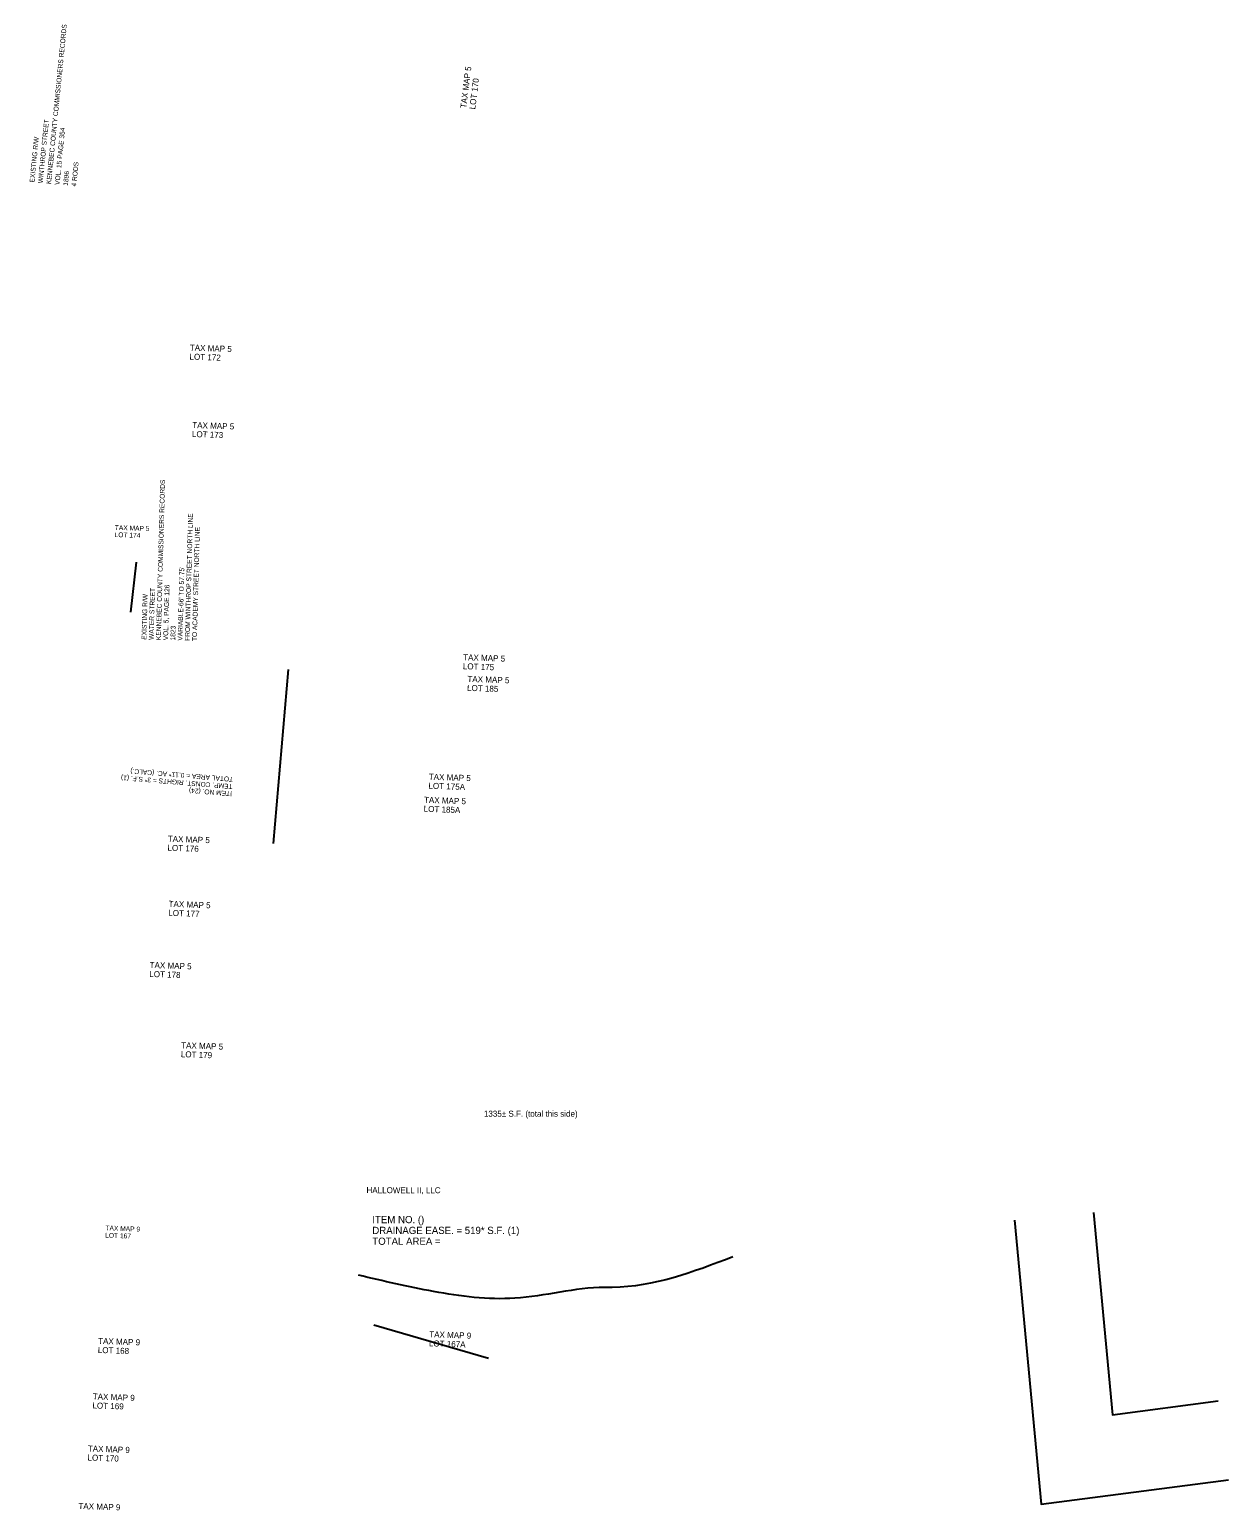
# Model space of a CAD drawing. Extents: x 1133267 to 1139526, y 528613 to 531538.
# Drawn here: x 1137644 to 1138142, y 529871 to 530487 of the extents above; entities that cross this region are included whole.
import ezdxf

# ---------------------------------------------------------------- set-up
doc = ezdxf.new("R2010")
doc.units = 0
for name, color, linetype in [('E_Property_Line', 7, 'Continuous'), ('E_ROW_TieLine', 7, 'Continuous'), ('P_Ease_Perm_Drainage_Line', 7, 'Continuous'), ('PROPERTY NOTES', 7, 'Continuous'), ('PRP OWNER NAMES', 7, 'Continuous'), ('PRPTY SETUPS', 7, 'Continuous'), ('ROW REFERENCES', 7, 'Continuous')]:
    doc.layers.add(name, color=color, linetype=linetype)

msp = doc.modelspace()

# ---------------------------------------------------------------- linework, layer by layer
at = {"layer": 'E_Property_Line'}
for p, q in [((1137685.86, 530244.99), (1137688.14, 530265.71)), ((1137745.12, 530148.68), (1137751.44, 530221.17))]:
    msp.add_line(p, q, dxfattribs=at)
at = {"layer": 'E_ROW_TieLine'}
msp.add_line((1137834.58, 529934.58), (1137787, 529948.38), dxfattribs=at)
for points in [[(1138086.29, 529995.24), (1138094.25, 529911.19), (1138138.21, 529916.91)], [(1138053.43, 529992.13), (1138064.62, 529874.06), (1138142.46, 529884.18)]]:
    msp.add_lwpolyline(points, dxfattribs=at)
msp.add_spline([(1137936.27, 529976.83), (1137886.15, 529964.15), (1137883.05, 529964.15), (1137845.61, 529959.64), (1137811.82, 529962.46), (1137780.57, 529969.22)], degree=3, dxfattribs=at)

# ---------------------------------------------------------------- texts
at = {"layer": 'P_Ease_Perm_Drainage_Line'}
msp.add_text('1335± S.F. (total this side)', height=2.5, dxfattribs=at).set_placement((1137832.73, 530035.13))
at = {"layer": 'PROPERTY NOTES'}
for s, height, rotation, p in [('TAX MAP 5', 2.5, 82.95839, (1137825.38, 530454.39)), ('LOT 170', 2.5, 82.95839, (1137829.11, 530453.93)), ('LOT 172', 2.5, 357.92813, (1137710.21, 530350.01)), ('TAX MAP 5', 2.5, 357.92813, (1137710.34, 530353.76)), ('LOT 173', 2.5, 357.92813, (1137711.23, 530317.8)), ('TAX MAP 5', 2.5, 357.92813, (1137711.37, 530321.55)), ('LOT 174', 2, 357.92813, (1137679.03, 530276.2)), ('TAX MAP 5', 2, 357.92813, (1137679.13, 530279.2)), ('LOT 175', 2.5, 357.92813, (1137823.94, 530221.26)), ('TAX MAP 5', 2.5, 357.92813, (1137824.07, 530225)), ('TAX MAP 5', 2.5, 357.92813, (1137825.83, 530215.99)), ('LOT 185', 2.5, 357.92813, (1137825.69, 530212.24)), ('LOT 175A', 2.5, 357.92813, (1137809.62, 530171.56)), ('TAX MAP 5', 2.5, 357.92813, (1137809.76, 530175.3)), ('TAX MAP 5', 2.5, 357.92813, (1137807.77, 530165.69)), ('LOT 185A', 2.5, 357.92813, (1137807.64, 530161.94)), ('LOT 176', 2.5, 357.92813, (1137701.05, 530145.76)), ('TAX MAP 5', 2.5, 357.92813, (1137701.19, 530149.51)), ('TAX MAP 5', 2.5, 357.92813, (1137701.52, 530122.44)), ('LOT 177', 2.5, 357.92813, (1137701.38, 530118.7)), ('TAX MAP 5', 2.5, 357.92813, (1137693.62, 530097.03)), ('LOT 178', 2.5, 357.92813, (1137693.48, 530093.28)), ('LOT 179', 2.5, 357.92813, (1137706.61, 530059.91)), ('TAX MAP 5', 2.5, 357.92813, (1137706.74, 530063.65)), ('TAX MAP 9', 2, 357.92813, (1137675.25, 529987.89)), ('LOT 167', 2, 357.92813, (1137675.14, 529984.87)), ('TAX MAP 9', 2.5, 357.92813, (1137809.95, 529943.44)), ('LOT 168', 2.5, 357.92813, (1137672.06, 529936.91)), ('TAX MAP 9', 2.5, 357.92813, (1137672.2, 529940.66)), ('LOT 167A', 2.5, 357.92813, (1137809.82, 529939.69)), ('TAX MAP 9', 2.5, 357.92813, (1137669.97, 529917.58)), ('LOT 169', 2.5, 357.92813, (1137669.83, 529913.84)), ('TAX MAP 9', 2.5, 357.92813, (1137667.92, 529895.93)), ('LOT 170', 2.5, 357.92813, (1137667.78, 529892.18)), ('TAX MAP 9', 2.5, 357.92813, (1137663.99, 529872.06))]:
    msp.add_text(s, height=height, rotation=rotation, dxfattribs=at).set_placement(p)
at = {"layer": 'PRP OWNER NAMES'}
msp.add_text('HALLOWELL II, LLC', height=2.5, rotation=359.95317, dxfattribs=at).set_placement((1137783.87, 530003.34))
at = {"layer": 'PRPTY SETUPS'}
for s, p in [('TOTAL AREA = 0.11* AC. (CALC.)', (1137728.48, 530176.38)), ('TEMP. CONST. RIGHTS = 3* S.F. (1)', (1137728.23, 530173.37)), ('ITEM NO. (24)', (1137727.99, 530170.36))]:
    msp.add_text(s, height=2, rotation=175.39044, dxfattribs=at).set_placement(p)
for s, p in [('ITEM NO. ()', (1137786.3, 529990.86)), ('DRAINAGE EASE. = 519* S.F. (1)', (1137786.3, 529986.36)), ('TOTAL AREA =', (1137786.3, 529981.86))]:
    msp.add_text(s, height=3, dxfattribs=at).set_placement(p)
at = {"layer": 'ROW REFERENCES'}
for s, rotation, p in [('KENNEBEC COUNTY COMMISSIONERS RECORDS', 84.34851, (1137652.65, 530422.89)), ('WINTHROP STREET', 84.34851, (1137649.17, 530423.24)), ('VOL. 15 PAGE 354', 84.34851, (1137656.14, 530422.55)), ('EXISTING R/W', 84.34851, (1137645.69, 530423.58)), ('4 RODS', 84.34851, (1137663.1, 530421.86)), ('1896', 84.34851, (1137659.62, 530422.21)), ('KENNEBEC COUNTY COMMISSIONERS RECORDS', 88.47432, (1137698.3, 530233.31)), ('FROM WINTHROP STREET NORTH LINE', 88.47432, (1137710.29, 530232.99)), ('TO ACADEMY STREET NORTH LINE', 88.47432, (1137713.29, 530232.91)), ("VARIABLE-66' TO 57.75'", 88.47432, (1137707.29, 530233.07)), ('WATER STREET', 88.47432, (1137695.3, 530233.39)), ('VOL. 5, PAGE 126', 88.47432, (1137701.29, 530233.23)), ('EXISTING R/W', 88.47432, (1137692.3, 530233.47)), ('1823', 88.47432, (1137704.29, 530233.15))]:
    msp.add_text(s, height=2, rotation=rotation, dxfattribs=at).set_placement(p)

doc.saveas('drawing.dxf')
